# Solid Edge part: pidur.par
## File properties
Title: pidur
Author: Stella-Marii
Template: iso metric part.par
Last saved by: Stella-Marii
Revision: 6
Application: Solid Edge
Document Number: 28
Density: 1024,000 kg/m^3
Accuracy: 0,990
Username: Stella-Marii
Material: ABS Plastic, high impact
Face Style: Red
Fill Style: ANSI34(Plastic)
Virtual Style: Red (Shiny)
Grouping: Non-metals\Plastics
LibraryName: Materials
Coef. of Thermal Exp: 9e-05
Thermal Conductivity: 0.2
Specific Heat: 0.0
Modulus of Elasticity: 1378951400.0
Poisson's Ratio: 0.4
Yield Stress: 31026406.5
Ultimate Stress: 0.0
Elongation: 0.0
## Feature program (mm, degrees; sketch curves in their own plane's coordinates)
lofted protrusion "unnamed LoftedProtrusion 1"
fillet "Round_1" radius 2
fillet "Round_2" radius 1
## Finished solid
Body 1: solid body, 10 faces, 24 edges, 16 vertices.
  Faces by surface: blend 4, plane 3, spline 3
  Edges by curve: intersection 16, line 8
Bounding box of the edges (mm; curved faces can reach further): 17.000 x 16.988 x 85.168, from (-8.5, -8.4937, 0) to (8.5, 8.4937, 85.1677).
Planar faces by outward normal: +x 1, +z 1, -z 1
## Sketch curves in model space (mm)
line (2.27, -3.5, 85.1677) -> (8.5, -3.5, 85.1677)
line (8.5, -3.5, 85.1677) -> (8.5, 3.5, 85.1677)
line (8.5, 3.5, 85.1677) -> (2.27, 3.5, 85.1677)
line (2.27, 3.5, 85.1677) -> (2.27, -3.5, 85.1677)
line (8.5, -4.3124, 72.4735) -> (1.5461, -4.3124, 72.4735)
line (1.5461, -4.3124, 72.4735) -> (1.5461, 4.3124, 72.4735)
line (1.5461, 4.3124, 72.4735) -> (8.5, 4.3124, 72.4735)
line (8.5, 4.3124, 72.4735) -> (8.5, -4.3124, 72.4735)
line (8.5, -6.2416, 27.3342) -> (0.6621, -6.2416, 27.3342)
line (0.6621, -6.2416, 27.3342) -> (0.6621, 6.2416, 27.3342)
line (0.6621, 6.2416, 27.3342) -> (8.5, 6.2416, 27.3342)
line (8.5, 6.2416, 27.3342) -> (8.5, -6.2416, 27.3342)
line (1.5461, -4.3124, 21.911) -> (8.5, -4.3124, 21.911)
line (1.5461, 4.3124, 21.911) -> (1.5461, -4.3124, 21.911)
line (8.5, 4.3124, 21.911) -> (1.5461, 4.3124, 21.911)
line (8.5, 4.3124, 21.911) -> (8.5, -4.3124, 21.911)
line (2.27, 3.5, 16.3392) -> (2.27, -3.5, 16.3392)
line (2.27, -3.5, 16.3392) -> (8.5, -3.5, 16.3392)
line (8.5, -3.5, 16.3392) -> (8.5, 3.5, 16.3392)
line (8.5, 3.5, 16.3392) -> (2.27, 3.5, 16.3392)
line (8.5, -3.5, 11.2816) -> (-4.0289, -3.5, 11.2816)
line (-4.0289, -3.5, 11.2816) -> (-4.0289, 3.5, 11.2816)
line (-4.0289, 3.5, 11.2816) -> (8.5, 3.5, 11.2816)
line (8.5, 3.5, 11.2816) -> (8.5, -3.5, 11.2816)
line (8.5, -3.5, 5.7098) -> (-5.9011, -3.5, 5.7098)
line (-5.9011, -3.5, 5.7098) -> (-5.9011, 3.5, 5.7098)
line (-5.9011, 3.5, 5.7098) -> (8.5, 3.5, 5.7098)
line (8.5, 3.5, 5.7098) -> (8.5, -3.5, 5.7098)
line (8.5, -3.5, 0) -> (8.5, 3.5, 0)
line (8.5, 3.5, 0) -> (-8.5, 3.5, 0)
line (-8.5, 3.5, 0) -> (-8.5, -3.5, 0)
line (-8.5, -3.5, 0) -> (8.5, -3.5, 0)
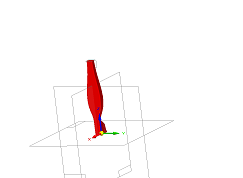
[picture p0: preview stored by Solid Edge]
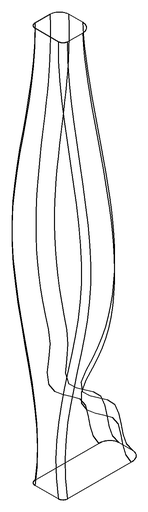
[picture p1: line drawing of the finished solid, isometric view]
